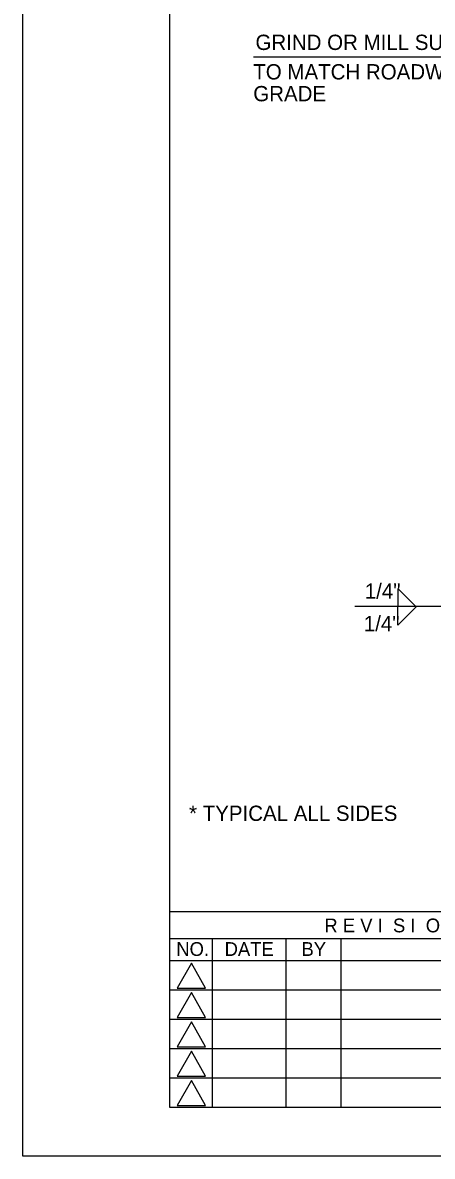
# Model space of a CAD drawing. Extents: x 0 to 22.7, y 0 to 15.7.
# Drawn here: x 0 to 2.79, y 0 to 7.72 of the extents above; entities that cross this region are included whole.
import ezdxf

# ---------------------------------------------------------------- set-up
doc = ezdxf.new("R2010")
doc.units = 0
for name, color, linetype in [('BORDER_ANNO_Cutsheet', 7, 'Continuous'), ('BRDG_ANNO_Anno-Sheet', 7, 'Continuous'), ('BRDG_ANNO_General-Notes', 7, 'Continuous'), ('BRDG_BASE_Active-Point', 7, 'Continuous')]:
    doc.layers.add(name, color=color, linetype=linetype)

msp = doc.modelspace()

# ---------------------------------------------------------------- linework, layer by layer
at = {"layer": 'BORDER_ANNO_Cutsheet'}
msp.add_lwpolyline([(0, 14.6667), (22.6667, 14.6667), (22.6667, 0), (0, 0)], close=True, dxfattribs=at)
at = {"layer": 'BRDG_ANNO_Anno-Sheet'}
for p, q in [((1, 1.6667), (12.8333, 1.6667)), ((1, 1.4833), (4.6667, 1.4833)), ((1.2917, 0.3333), (1.2917, 1.4833)), ((1.7917, 0.3333), (1.7917, 1.4833)), ((2.1667, 0.3333), (2.1667, 1.4796)), ((0.9983, 1.3333), (4.6667, 1.3333)), ((0.9983, 1.1333), (4.6667, 1.1333)), ((0.9983, 0.9333), (4.6667, 0.9333)), ((0.9983, 0.7333), (4.6667, 0.7333)), ((0.9983, 0.5333), (4.6667, 0.5333))]:
    msp.add_line(p, q, dxfattribs=at)
msp.add_lwpolyline([(1, 14.3333), (22.3333, 14.3333), (22.3333, 0.3333), (1, 0.3333)], close=True, dxfattribs=at)
for points in [[(1.1483, 1.3162), (1.0496, 1.145), (1.2429, 1.145), (1.1483, 1.3162)], [(1.1483, 1.1162), (1.0496, 0.945), (1.2429, 0.945), (1.1483, 1.1162)], [(1.1483, 0.9163), (1.0496, 0.745), (1.2429, 0.745), (1.1483, 0.9163)], [(1.1483, 0.7162), (1.0496, 0.545), (1.2429, 0.545), (1.1483, 0.7162)], [(1.1483, 0.5162), (1.0496, 0.345), (1.2429, 0.345), (1.1483, 0.5162)]]:
    msp.add_lwpolyline(points, dxfattribs=at)
at = {"layer": 'BRDG_ANNO_General-Notes'}
for p, q in [((3.4786, 7.4841), (1.5695, 7.4841)), ((2.5511, 3.8658), (2.5511, 3.7408)), ((2.5511, 3.8658), (2.6761, 3.7408)), ((2.2591, 3.7458), (3.2137, 3.7458)), ((2.5511, 3.6158), (2.5511, 3.7408)), ((2.5511, 3.6158), (2.6761, 3.7408))]:
    msp.add_line(p, q, dxfattribs=at)
at = {"layer": 'BRDG_BASE_Active-Point'}
msp.add_line((0, 0), (0, 0), dxfattribs=at)

# ---------------------------------------------------------------- texts
at = {"layer": 'BRDG_ANNO_Anno-Sheet'}
for s, p in [('R E V I  S I  O N S', (2.0516, 1.525)), ('NO.', (1.0444, 1.3646)), ('DATE', (1.3733, 1.3646)), ('BY', (1.8961, 1.3646))]:
    msp.add_text(s, height=0.09375, dxfattribs=at).set_placement(p)
at = {"layer": 'BRDG_ANNO_General-Notes'}
for s, height, p in [('GRIND OR MILL SURFACE', 0.104167, (1.5831, 7.5326)), ('TO MATCH ROADWAY', 0.104167, (1.5682, 7.3319)), ('GRADE', 0.10417, (1.5682, 7.1832)), ('1/4"', 0.10411, (2.3267, 3.7967)), ('1/4"', 0.10411, (2.32, 3.5753)), ('* TYPICAL ALL SIDES', 0.104167, (1.1315, 2.2836))]:
    msp.add_text(s, height=height, dxfattribs=at).set_placement(p)

doc.saveas('drawing.dxf')
